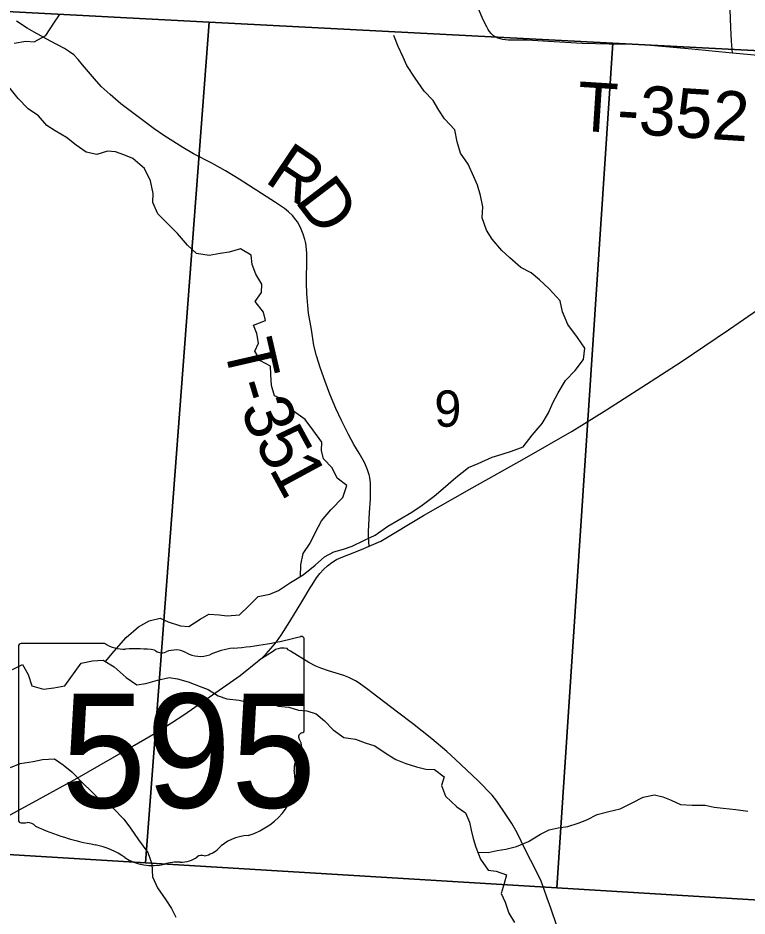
# Model space of a CAD drawing. Extents: x 39.8 to 73.8, y 13 to 35.
# Drawn here: x 47.463 to 48.304, y 29.851 to 30.888 of the extents above; entities that cross this region are included whole.
import ezdxf

# ---------------------------------------------------------------- set-up
doc = ezdxf.new("R2010")
doc.units = 0
for name, color, linetype in [('GM_X_Corporation', 7, 'Continuous'), ('GM_X_Minor_River', 7, 'Continuous'), ('GM_X_Section_Text', 7, 'Continuous'), ('GM_X_State_Location', 7, 'Continuous'), ('GM_X_State_Route', 7, 'Continuous'), ('GM_X_State_Shield', 7, 'Continuous'), ('GM_X_Township_Road', 7, 'Continuous'), ('GM_X_Township_Road_Text', 7, 'Continuous')]:
    doc.layers.add(name, color=color, linetype=linetype)

msp = doc.modelspace()

# ---------------------------------------------------------------- linework, layer by layer
at = {"layer": 'GM_X_Corporation'}
for points in [[(47.4415, 30.9593), (48.4569, 30.9045), (48.4524, 30.8427), (48.1497, 30.8585), (47.6837, 30.8829), (47.4356, 30.8958)], [(47.6837, 30.8829), (47.6104, 29.9124), (47.3755, 29.9267), (47.4356, 30.8958)], [(48.1497, 30.8585), (48.0851, 29.8835), (47.6104, 29.9124), (47.6837, 30.8829)], [(48.4524, 30.8427), (48.3814, 29.8655), (48.0851, 29.8835), (48.1497, 30.8585)], [(47.3645, 29.9274), (47.3755, 29.9267), (47.6104, 29.9124), (48.0851, 29.8835), (48.3814, 29.8655), (48.3118, 28.8573), (47.3001, 28.9116)]]:
    msp.add_lwpolyline(points, close=True, dxfattribs=at)
at = {"layer": 'GM_X_Minor_River'}
for p, q in [((47.5045, 30.8819), (47.5113, 30.8914)), ((47.4955, 30.8675), (47.5045, 30.8819)), ((47.4588, 30.8586), (47.4724, 30.8609)), ((47.4724, 30.8609), (47.4819, 30.8602)), ((47.4819, 30.8602), (47.4955, 30.8675)), ((47.9019, 30.8547), (47.8969, 30.8676)), ((47.9076, 30.8426), (47.9019, 30.8547)), ((47.9118, 30.8327), (47.9076, 30.8426)), ((47.9214, 30.8184), (47.9118, 30.8327)), ((47.932, 30.8032), (47.9214, 30.8184)), ((47.4636, 30.7949), (47.4526, 30.8081)), ((47.9423, 30.7923), (47.932, 30.8032)), ((47.475, 30.7828), (47.4636, 30.7949)), ((47.9488, 30.7813), (47.9423, 30.7923)), ((47.4868, 30.7749), (47.475, 30.7828)), ((47.4967, 30.7635), (47.4868, 30.7749)), ((47.9553, 30.7714), (47.9488, 30.7813)), ((47.9671, 30.7586), (47.9553, 30.7714)), ((47.5062, 30.7575), (47.4967, 30.7635)), ((47.5191, 30.7496), (47.5062, 30.7575)), ((47.9698, 30.7449), (47.9671, 30.7586)), ((47.5305, 30.7409), (47.5191, 30.7496)), ((47.974, 30.7317), (47.9698, 30.7449)), ((47.5419, 30.7326), (47.5305, 30.7409)), ((47.5665, 30.7338), (47.5544, 30.7299)), ((47.576, 30.733), (47.5665, 30.7338)), ((47.5855, 30.7297), (47.576, 30.733)), ((47.5544, 30.7299), (47.5419, 30.7326)), ((47.5957, 30.7255), (47.5855, 30.7297)), ((47.6094, 30.7138), (47.5957, 30.7255)), ((47.9828, 30.7188), (47.974, 30.7317)), ((47.6163, 30.6998), (47.6094, 30.7138)), ((47.9893, 30.7044), (47.9828, 30.7188)), ((47.9935, 30.6945), (47.9893, 30.7044)), ((47.6194, 30.685), (47.6163, 30.6998)), ((47.9969, 30.6828), (47.9935, 30.6945)), ((47.619, 30.6748), (47.6194, 30.685)), ((47.9996, 30.6695), (47.9969, 30.6828)), ((47.6248, 30.6615), (47.619, 30.6748)), ((47.6362, 30.6502), (47.6248, 30.6615)), ((47.9989, 30.657), (47.9996, 30.6695)), ((47.6472, 30.6388), (47.6362, 30.6502)), ((48.0039, 30.6426), (47.9989, 30.657)), ((48.0104, 30.6324), (48.0039, 30.6426)), ((47.659, 30.6256), (47.6472, 30.6388)), ((48.0214, 30.6191), (48.0104, 30.6324)), ((47.6693, 30.6157), (47.659, 30.6256)), ((47.72, 30.6212), (47.7068, 30.6174)), ((47.7325, 30.6137), (47.72, 30.6212)), ((48.0309, 30.6108), (48.0214, 30.6191)), ((47.6837, 30.6135), (47.6693, 30.6157)), ((47.6965, 30.6158), (47.6837, 30.6135)), ((47.7068, 30.6174), (47.6965, 30.6158)), ((47.7333, 30.6031), (47.7325, 30.6137)), ((48.0435, 30.5995), (48.0309, 30.6108)), ((47.7379, 30.5921), (47.7333, 30.6031)), ((48.0552, 30.5935), (48.0435, 30.5995)), ((47.7448, 30.5803), (47.7379, 30.5921)), ((48.0651, 30.5855), (48.0552, 30.5935)), ((47.7441, 30.5708), (47.7448, 30.5803)), ((48.0762, 30.5749), (48.0651, 30.5855)), ((47.7369, 30.5602), (47.7441, 30.5708)), ((48.0887, 30.5613), (48.0762, 30.5749)), ((47.7464, 30.5481), (47.7369, 30.5602)), ((48.0914, 30.5484), (48.0887, 30.5613)), ((47.7488, 30.5386), (47.7464, 30.5481)), ((48.0975, 30.534), (48.0914, 30.5484)), ((47.7351, 30.5329), (47.7488, 30.5386)), ((47.739, 30.5234), (47.7351, 30.5329)), ((48.1086, 30.5189), (48.0975, 30.534)), ((47.7409, 30.5124), (47.739, 30.5234)), ((48.1173, 30.5064), (48.1086, 30.5189)), ((47.7364, 30.5029), (47.7409, 30.5124)), ((48.1159, 30.4935), (48.1173, 30.5064)), ((47.7429, 30.4919), (47.7364, 30.5029)), ((47.7547, 30.4859), (47.7429, 30.4919)), ((47.7551, 30.476), (47.7547, 30.4859)), ((48.1061, 30.4806), (48.1159, 30.4935)), ((47.7559, 30.4635), (47.7551, 30.476)), ((48.0948, 30.4692), (48.1061, 30.4806)), ((47.7594, 30.4514), (47.7559, 30.4635)), ((48.0865, 30.4551), (48.0948, 30.4692)), ((48.0805, 30.4433), (48.0865, 30.4551)), ((47.7688, 30.4473), (47.7594, 30.4514)), ((47.781, 30.4336), (47.7688, 30.4473)), ((48.0753, 30.4319), (48.0805, 30.4433)), ((47.7947, 30.4242), (47.781, 30.4336)), ((47.8034, 30.4121), (47.7947, 30.4242)), ((48.0681, 30.4194), (48.0753, 30.4319)), ((47.8137, 30.3981), (47.8034, 30.4121)), ((48.0564, 30.4061), (48.0681, 30.4194)), ((48.0463, 30.3924), (48.0564, 30.4061)), ((47.8134, 30.3882), (47.8137, 30.3981)), ((48.0327, 30.3874), (48.0463, 30.3924)), ((47.8157, 30.3787), (47.8134, 30.3882)), ((47.9941, 30.3732), (48.0103, 30.3805)), ((48.0103, 30.3805), (48.0217, 30.384)), ((48.0217, 30.384), (48.0327, 30.3874)), ((47.8256, 30.3682), (47.8157, 30.3787)), ((47.9831, 30.3687), (47.9941, 30.3732)), ((47.8317, 30.3564), (47.8256, 30.3682)), ((47.9684, 30.3572), (47.9831, 30.3687)), ((47.8427, 30.3481), (47.8317, 30.3564)), ((47.9537, 30.3443), (47.9684, 30.3572)), ((47.8382, 30.3341), (47.8427, 30.3481)), ((47.9435, 30.3355), (47.9537, 30.3443)), ((47.8243, 30.32), (47.8382, 30.3341)), ((47.9295, 30.3252), (47.9435, 30.3355)), ((47.8134, 30.307), (47.8243, 30.32)), ((47.9175, 30.3172), (47.9295, 30.3252)), ((47.8899, 30.3008), (47.902, 30.3081)), ((47.902, 30.3081), (47.9175, 30.3172)), ((47.8066, 30.2941), (47.8134, 30.307)), ((47.8752, 30.2905), (47.8899, 30.3008)), ((47.8002, 30.2812), (47.8066, 30.2941)), ((47.8631, 30.2848), (47.8752, 30.2905)), ((47.7923, 30.2694), (47.8002, 30.2812)), ((47.8389, 30.2745), (47.8487, 30.2779)), ((47.8487, 30.2779), (47.8631, 30.2848)), ((47.7897, 30.2565), (47.7923, 30.2694)), ((47.817, 30.2657), (47.8275, 30.2714)), ((47.8275, 30.2714), (47.8389, 30.2745)), ((47.7892, 30.2428), (47.7897, 30.2565)), ((47.806, 30.2558), (47.817, 30.2657)), ((47.7924, 30.2448), (47.806, 30.2558)), ((47.7637, 30.2268), (47.7777, 30.236)), ((47.7777, 30.236), (47.7924, 30.2448)), ((47.7539, 30.2226), (47.7637, 30.2268)), ((47.7297, 30.2089), (47.7403, 30.2199)), ((47.7403, 30.2199), (47.7539, 30.2226)), ((47.7188, 30.1986), (47.7297, 30.2089)), ((47.6147, 30.1915), (47.6272, 30.1949)), ((47.6272, 30.1949), (47.6366, 30.1904)), ((47.6734, 30.1936), (47.6836, 30.1993)), ((47.6836, 30.1993), (47.6953, 30.1986)), ((47.6953, 30.1986), (47.7048, 30.1974)), ((47.7048, 30.1974), (47.7188, 30.1986)), ((47.5882, 30.1724), (47.6022, 30.1846)), ((47.6022, 30.1846), (47.6147, 30.1915)), ((47.6366, 30.1904), (47.6507, 30.1859)), ((47.6507, 30.1859), (47.6605, 30.1852)), ((47.6605, 30.1852), (47.6734, 30.1936)), ((47.5743, 30.1568), (47.5882, 30.1724)), ((47.5641, 30.1446), (47.5743, 30.1568)), ((47.4658, 30.0271), (47.4809, 30.0291)), ((47.4809, 30.0291), (47.4915, 30.0314)), ((47.4915, 30.0314), (47.5055, 30.0322)), ((47.5055, 30.0322), (47.5154, 30.0254)), ((47.4548, 30.0225), (47.4658, 30.0271)), ((47.5154, 30.0254), (47.5253, 30.0174)), ((47.5253, 30.0174), (47.5375, 30.005)), ((47.5375, 30.005), (47.561, 29.9823)), ((48.1719, 29.9816), (48.1847, 29.9881)), ((48.1847, 29.9881), (48.1976, 29.9908)), ((48.1976, 29.9908), (48.2074, 29.9885)), ((48.2074, 29.9885), (48.2169, 29.9847)), ((47.561, 29.9823), (47.5732, 29.9755)), ((48.1579, 29.9747), (48.1719, 29.9816)), ((48.2169, 29.9847), (48.2275, 29.9795)), ((48.2275, 29.9795), (48.2412, 29.9788)), ((48.2412, 29.9788), (48.2559, 29.9788)), ((48.2559, 29.9788), (48.2665, 29.9766)), ((48.2665, 29.9766), (48.2768, 29.9755)), ((47.5732, 29.9755), (47.5854, 29.9626)), ((48.1197, 29.9621), (48.1314, 29.9682)), ((48.1314, 29.9682), (48.145, 29.9716)), ((48.145, 29.9716), (48.1579, 29.9747)), ((48.2768, 29.9755), (48.2916, 29.974)), ((48.2916, 29.974), (48.3052, 29.9721)), ((47.5854, 29.9626), (47.593, 29.9524)), ((48.0978, 29.9544), (48.1095, 29.9579)), ((48.1095, 29.9579), (48.1197, 29.9621)), ((47.593, 29.9524), (47.6025, 29.9388)), ((48.0524, 29.9368), (48.066, 29.9452)), ((48.066, 29.9452), (48.0762, 29.9505)), ((48.0762, 29.9505), (48.0864, 29.9528)), ((48.0864, 29.9528), (48.0978, 29.9544)), ((47.6025, 29.9388), (47.6132, 29.9244)), ((48.0384, 29.9311), (48.0524, 29.9368)), ((47.6132, 29.9244), (47.6178, 29.9111)), ((47.9937, 29.9246), (48.0059, 29.9241)), ((48.0059, 29.9241), (48.0161, 29.9264)), ((48.0161, 29.9264), (48.0263, 29.928)), ((48.0263, 29.928), (48.0384, 29.9311)), ((47.6178, 29.9111), (47.6186, 29.8963)), ((47.6186, 29.8963), (47.6243, 29.8835)), ((47.6243, 29.8835), (47.6339, 29.8695)), ((47.6339, 29.8695), (47.6403, 29.8596)), ((47.6403, 29.8596), (47.6453, 29.8494))]:
    msp.add_line(p, q, dxfattribs=at)
for points in [[(47.457, 30.1356), (47.4687, 30.1413), (47.4752, 30.1299), (47.4794, 30.1167), (47.4927, 30.1129), (47.5048, 30.1145), (47.5173, 30.1168), (47.5361, 30.1427), (47.5494, 30.1454), (47.5615, 30.1462), (47.5744, 30.1386), (47.5881, 30.1261), (47.6006, 30.1178), (47.6108, 30.1194), (47.6244, 30.1232), (47.6377, 30.1263), (47.6475, 30.1248), (47.6597, 30.1214), (47.6733, 30.1158), (47.6828, 30.1124), (47.6942, 30.1052), (47.7044, 30.1018), (47.7185, 30.1), (47.7294, 30.0974), (47.7423, 30.1001), (47.7537, 30.0971), (47.7635, 30.0933), (47.7757, 30.0922), (47.787, 30.0885), (47.7965, 30.0877), (47.8075, 30.0843), (47.817, 30.0764), (47.8269, 30.0658), (47.8394, 30.0568), (47.8527, 30.0549), (47.8637, 30.0508), (47.8751, 30.0474)], [(47.8751, 30.0474), (47.8891, 30.0376), (47.8994, 30.0315), (47.9108, 30.027), (47.9229, 30.0233), (47.9339, 30.0206), (47.9437, 30.0199), (47.9548, 30.0116), (47.9518, 30.0017), (47.9564, 29.9892), (47.9697, 29.9771), (47.9795, 29.97), (47.9841, 29.9593), (47.9861, 29.9499), (47.9884, 29.9404), (47.9915, 29.9305), (47.9968, 29.9165), (48.0056, 29.904), (48.0151, 29.9025), (48.0268, 29.8984), (48.0242, 29.8885), (48.0208, 29.8768), (48.0254, 29.8669), (48.0296, 29.854), (48.0361, 29.8434)]]:
    msp.add_lwpolyline(points, dxfattribs=at)
at = {"layer": 'GM_X_State_Route'}
msp.add_lwpolyline([(47.4277, 29.9535), (47.4764, 29.9798), (47.5315, 30.0101), (47.5978, 30.0483), (47.6263, 30.0646), (47.6545, 30.0831), (47.684, 30.1036), (47.7198, 30.1286), (47.7417, 30.1461), (47.7453, 30.1493), (47.7496, 30.1536), (47.7578, 30.1628), (47.7616, 30.1676), (47.7669, 30.1752), (47.7768, 30.1909), (47.7908, 30.2138), (47.8004, 30.2298), (47.8026, 30.2334), (47.8078, 30.2412), (47.8116, 30.2462), (47.8157, 30.2509), (47.8203, 30.2553), (47.8253, 30.2591), (47.8307, 30.2624), (47.8363, 30.265), (47.8451, 30.2684), (47.8596, 30.2739), (47.8684, 30.2778), (47.882, 30.2838), (47.9313, 30.3133), (47.9872, 30.3454), (48.0475, 30.379), (48.1026, 30.4107), (48.1424, 30.4353), (48.1831, 30.4614), (48.2283, 30.4909), (48.2829, 30.5275), (48.3399, 30.567)], dxfattribs=at)
at = {"layer": 'GM_X_State_Shield'}
for p, q in [((47.5637, 30.1654), (47.4672, 30.1654)), ((47.7936, 30.0657), (47.7936, 30.1703)), ((47.464, 30.1619), (47.464, 29.9618)), ((47.7935, 30.0657), (47.7936, 30.0657))]:
    msp.add_line(p, q, dxfattribs=at)
for centre, major_axis, start_param, end_param in [((47.6762, 30.4382), (0.3495, 0), 4.814394, 5.042369), ((47.7899, 30.1708), (0.00367, 0), 6.141152, 7.989035), ((47.4677, 30.1624), (0.00382, 0), 1.712693, 3.28349), ((47.5867, 30.1886), (0.037, 0), 4.042523, 4.731795), ((47.599, 30.053), (0.133, 0), 1.404758, 1.657858), ((47.6292, 30.1634), (0.0107, 0), 3.836095, 5.185415), ((47.6449, 30.1403), (0.0222, 0), 0.950623, 2.079405), ((47.6735, 30.172), (0.0267, 0), 4.081561, 5.145723), ((47.7207, 30.1043), (0.0703, 0), 1.699011, 2.107814), ((47.7927, 30.058), (0.00568, 0), 1.883978, 3.671073), ((47.7896, 30.0652), (0.00393, 0), 5.05454, 6.418171), ((47.7566, 30.0447), (0.0341, 0), 5.934695, 6.695948), ((47.8067, 30.0218), (0.0248, 0), 2.387724, 3.262537), ((47.6957, 30.0085), (0.0874, 0), 5.101752, 6.440018), ((47.4678, 29.9614), (0.00385, 0), 3.00124, 4.508301), ((47.4684, 29.9819), (0.0294, 0), 4.665946, 4.897461), ((47.4744, 29.9503), (0.0106, 0), 0.519207, 1.627899), ((47.6082, 30.1301), (0.2524, 0), 4.195997, 4.488961), ((47.7326, 29.9056), (0.0479, 0), 1.647645, 2.488434), ((47.533, 29.8719), (0.079, 0), 0.823519, 1.323587), ((47.6719, 29.9424), (0.0282, 0), 4.937069, 5.64225), ((47.6184, 29.9493), (0.0501, 0), 4.026481, 4.996735), ((47.651, 29.9343), (0.0267, 0), 4.691044, 5.507374), ((47.6751, 29.9149), (0.00752, 0), 1.147584, 2.315152), ((47.6473, 29.8801), (0.0412, 0), 1.495662, 1.94098)]:
    msp.add_ellipse(centre, major_axis=major_axis, ratio=0.8, start_param=start_param, end_param=end_param, dxfattribs=at)
at = {"layer": 'GM_X_Township_Road'}
for points in [[(48.2876, 30.847), (48.2405, 30.8517), (48.1975, 30.8557), (48.1792, 30.857), (48.1453, 30.8576), (48.1142, 30.8582), (48.0753, 30.8607), (48.0506, 30.862), (48.0382, 30.8621), (48.0289, 30.8622), (48.0228, 30.8628), (48.0198, 30.8635), (48.0169, 30.8645), (48.0141, 30.8658), (48.0116, 30.8676), (48.0093, 30.8697), (48.0073, 30.8721), (48.0056, 30.8746), (48.0041, 30.8773), (48.0001, 30.8857), (47.988, 30.9142)], [(48.3399, 30.567), (48.3418, 30.597), (48.3475, 30.6653), (48.3503, 30.6994), (48.3543, 30.7772), (48.3547, 30.7958), (48.3566, 30.8238), (48.3565, 30.8269), (48.3562, 30.83), (48.3553, 30.8329), (48.3539, 30.8357), (48.352, 30.8381), (48.3495, 30.8399), (48.3482, 30.8405), (48.3461, 30.8411), (48.3372, 30.8427), (48.3247, 30.8438), (48.3089, 30.8451), (48.2876, 30.847), (48.2865, 30.8611), (48.2856, 30.8768), (48.285, 30.8976)], [(47.8684, 30.2778), (47.8679, 30.283), (47.8676, 30.2886), (47.8676, 30.295), (47.869, 30.3167), (47.87, 30.3322), (47.8701, 30.3415), (47.8698, 30.3508), (47.8692, 30.357), (47.8685, 30.3601), (47.8667, 30.366), (47.8643, 30.3717), (47.863, 30.3745), (47.8614, 30.3771), (47.8568, 30.3852), (47.8509, 30.3954), (47.8445, 30.407), (47.8364, 30.4229), (47.8299, 30.437), (47.8231, 30.4535), (47.8177, 30.4682), (47.8123, 30.4829), (47.8078, 30.4978), (47.8048, 30.5097), (47.8019, 30.5279), (47.7985, 30.5468), (47.7967, 30.5694), (47.7963, 30.5821), (47.7963, 30.5891), (47.7963, 30.5946), (47.7964, 30.5979), (47.7964, 30.601), (47.7966, 30.6073), (47.7966, 30.6134), (47.7964, 30.6167), (47.7954, 30.6276), (47.7951, 30.629), (47.7943, 30.6318), (47.7924, 30.6383), (47.7901, 30.644), (47.7873, 30.6496), (47.7857, 30.6523), (47.7839, 30.6548), (47.78, 30.6596), (47.7755, 30.6639), (47.7707, 30.6678), (47.7604, 30.6746), (47.7186, 30.7017), (47.7026, 30.7112), (47.6868, 30.7199), (47.6657, 30.731), (47.6536, 30.7381), (47.6418, 30.7456), (47.6315, 30.7521), (47.6206, 30.7597), (47.602, 30.7736), (47.5895, 30.7829), (47.582, 30.7884), (47.5695, 30.7994), (47.5594, 30.8086), (47.5514, 30.8173), (47.5378, 30.8336), (47.5327, 30.8398), (47.5277, 30.8452), (47.5228, 30.8488), (47.517, 30.8526), (47.5007, 30.861), (47.4818, 30.8714), (47.4739, 30.8761), (47.4617, 30.8841)], [(48.085, 29.8395), (48.0782, 29.86), (48.0738, 29.8716), (48.0703, 29.8815), (48.0668, 29.8911), (48.0622, 29.9008), (48.0548, 29.915), (48.0486, 29.9276), (48.039, 29.9469), (48.033, 29.9577), (48.0263, 29.9682), (48.0157, 29.9834), (48.0102, 29.9906), (47.9943, 30.0068), (47.9678, 30.0319), (47.9581, 30.0408), (47.9408, 30.0556), (47.9185, 30.073), (47.9013, 30.0862), (47.8721, 30.1086), (47.867, 30.1124), (47.8571, 30.1197), (47.8526, 30.1224), (47.8451, 30.1262), (47.8393, 30.1287), (47.8304, 30.1314), (47.8215, 30.1339), (47.8127, 30.1369), (47.8071, 30.1394), (47.799, 30.1437), (47.7778, 30.1566), (47.7752, 30.1583), (47.7739, 30.1599), (47.7703, 30.1601), (47.7663, 30.16), (47.7633, 30.1595), (47.7605, 30.1584), (47.7579, 30.1567), (47.7509, 30.1521), (47.7417, 30.1461)]]:
    msp.add_lwpolyline(points, dxfattribs=at)

# ---------------------------------------------------------------- texts
at = {"layer": 'GM_X_Section_Text'}
msp.add_text('9', height=0.0419, rotation=0, dxfattribs=at).set_placement((47.9436, 30.4158))
at = {"layer": 'GM_X_State_Location'}
for s in ['s', 'r']:
    msp.add_text(s, height=0.000189, dxfattribs=at).set_placement((47.6251, 30.0486))
msp.add_text('595', height=0.000189, rotation=0, dxfattribs=at).set_placement((47.5582, 30.0348))
at = {"layer": 'GM_X_State_Shield'}
msp.add_text('595', height=0.13184, dxfattribs=at).set_placement((47.5131, 29.9759))
at = {"layer": 'GM_X_Township_Road_Text'}
for s, height, rotation, p in [('T-352', 0.05682, 356.3536, (48.1069, 30.7578)), ('R', 0.0568, 326.0631, (47.7464, 30.6992)), ('D', 0.0568, 307.358, (47.7816, 30.6765)), ('T', 0.0568, 282.9937, (47.7003, 30.5097)), ('-', 0.0568, 286.7518, (47.7109, 30.4643)), ('3', 0.0568, 291.8658, (47.7194, 30.4368)), ('5', 0.0568, 298.6312, (47.7356, 30.3977)), ('1', 0.0568, 298.4668, (47.7523, 30.367))]:
    msp.add_text(s, height=height, rotation=rotation, dxfattribs=at).set_placement(p)

doc.saveas('drawing.dxf')
